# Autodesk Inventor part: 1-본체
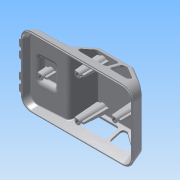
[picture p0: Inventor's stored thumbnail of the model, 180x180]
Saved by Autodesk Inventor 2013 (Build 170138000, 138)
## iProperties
Created: 2015-05
Part Number: 1-본체
Material: ABS 플라스틱
Document SubType Name: Modeling
Designer: Administrator
Density: 7.85 g/cm^3
Mass: 233.902 g
Surface Area: 305.679 cm^2
Volume: 29.7964 cm^3
Author: Administrator
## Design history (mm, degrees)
sketch "스케치1"
  geometry: L1 (0, 0)-(122, 0); L2 (42, 11.089)-(54.442, 31); L3 (54.442, 31)-(92, 31); L4 (92, 31)-(122, 11); L5 (118.738, 13.175)-(122, 1); L6 (2.144, 9)-(42, 11.089); L7 (122, 1)-(122, 0); L8 (0, 0)-(0, 1); L9 (0, 1)-(2.144, 9); L10 (0, 1)-(50, 1); L11 (0, 0)-(1, 0); L12 (1, 0)-(1, 1); L13 (1, 1)-(0, 1); L14 (0, 1)-(0, 0); L15 (122, 0)-(121, 0); L16 (121, 0)-(121, 1); L17 (121, 1)-(122, 1); L18 (122, 1)-(122, 0); L19 (122, 1)-(122, 13)
  constraints: 38 end point, 6 parallel, 3 horizontal, 3 perpendicular, 3 point on line, 1 collinear, 1 vertical
  dimensions: "d0" = 122 distance of L1.start L1.end; "d5" = 42 horizontal distance of L1.start L2.start; "d6" = 9 vertical distance of L1.start L6.start; "d7" = 125 deg angle of L2 L6; "d9" = 105 deg angle of L1 L5; "d19" = 1 distance of L1.start L8.end; "d20" = 1 distance of L5.end L1.end; "d21" = 105 deg angle of L1 L9; "d23" = 3 deg angle of L10 L6; "d24" = 1 distance of L1.start L11.end; "d25" = 1 distance of L15.end L16.end; "d26" = 1 distance of L16.end L17.end; "d70" = 30 horizontal distance of L5.end L3.end; "d76" = 31 distance between parallel lines of L1 L3; "d77" = 20 vertical distance of L3.end L4.end
extrude "돌출1" new body sketch "스케치1" stored distance "d15" = 76; taper "d16" = 0 deg
sketch "스케치3"
  geometry: L1 (13.175, 38)-(31, 38) reference; L2 (1, 38)-(13.175, 38) reference; L3 (31, -38)-(13.175, -38) reference; L4 (13.175, -38)-(1, -38) reference; L5 (31, -38)-(31, 38) reference; L6 (0, 38)-(1, 38) reference; L7 (1, -38)-(0, -38) reference; L8 (0, 38)-(1, 38); L9 (0, -38)-(1, -38); L10 (1, 38)-(31, 38); L11 (31, 38)-(31, 29.962); L12 (31, -29.962)-(31, -38); L13 (31, -38)-(1, -38); L14 (1, -38)-(1, 38) reference; L15 (31, -29.962)-(1, -38); L16 (31, 29.962)-(1, 38); 1 further point
  constraints: 16 end point, 3 collinear, 2 horizontal, 2 point on line
  dimensions: "d38" = 105 deg angle of L14 L16; "d39" = 15 deg angle of L3 L15; "d40" = 7.76457 distance from line of L1.end L16; "d41" = 65.64579 distance from line of L1.end L15
extrude "돌출3" cut sketch "스케치3" stored distance "d36" = 0; taper "d37" = 0 deg
fillet "모깎기1" dims "d42" = 12, "d44" = 3
fillet "모깎기2" dims "d45" = 3
sketch "스케치7"
  geometry: L1 (40.44, 11.007)-(13.137, 9.576) reference; L2 (10.985, 9.463)-(12.541, 14.552); L3 (12.541, 14.552)-(28.878, 15.408); L4 (28.878, 15.408)-(30.958, 10.51); L5 (10.985, 9.463)-(30.958, 10.51); L6 (4.32, 9.114)-(13.137, 9.576) reference; L7 (4.32, 9.114)-(-6, 8.573); L8 (0, 0)-(0, 8.888)
  constraints: 12 end point, 3 point on line, 1 collinear, 1 parallel, 1 vertical
  dimensions: "d59" = 70 deg angle of L1 L4; "d61" = 11 distance of L2.start L8.end; "d63" = 20 distance of L2.start L4.end; "d64" = 5 distance between parallel lines of L1 L3; "d101" = 70 deg angle of L6 L2
extrude "돌출4" join sketch "스케치7" stored distance "d65" = 26; taper "d66" = 0 deg
node "작업 평면1"
sketch "스케치15"
  geometry: L1 (13, 5)-(-13, 5) reference; L2 (-13, 0)-(-13, 5) reference; L3 (13, 5)-(13, 0) reference; L4 (-13, 0)-(-11.18, 5); L5 (-13, 5)-(-11.18, 5); L6 (-13, 5)-(-13, 0); L7 (11.18, 5)-(13, 0); L8 (13, 5)-(11.18, 5); L9 (13, 5)-(13, 0); L10 (24.829, 0)-(-24.829, 0) reference; 1 further point
  constraints: 12 end point, 3 collinear, 2 point on line, 1 perpendicular
  dimensions: "d108" = 70 deg angle of L10 L7; "d109" = 70 deg angle of L10 L4
extrude "돌출8" cut sketch "스케치15" distance "d110" = 35; taper "d111" = 0 deg
fillet "모깎기11" dims "d112" = 3
fillet "모깎기12" dims "d113" = 3
feature "쉘1" dims "d46" = 2
sketch "스케치5"
  geometry: L1 (53.253, 11)-(78.84, 11); L2 (81.84, 14)-(81.84, 23); L3 (78.84, 26)-(58.876, 26); L4 (56.332, 24.59)-(50.708, 15.59); L5 (91.092, 31)-(56.105, 31) reference; L6 (53.561, 29.59)-(42.828, 12.413) reference; L7 (107.213, 20.858)-(92.756, 30.496) reference; L8 (87.986, 11)-(103.078, 11); L9 (104.742, 16.496)-(91.242, 25.496); L10 (89.578, 26)-(87.986, 26); L11 (84.986, 23)-(84.986, 14); A1 r 3 centre (56.105, 28) between (56.105, 31) and (53.561, 29.59) reference; A2 r 3 centre (58.876, 23) between (58.876, 26) and (56.332, 24.59); A3 r 3 centre (78.84, 23) between (81.84, 23) and (78.84, 26); A4 r 3 centre (78.84, 14) between (78.84, 11) and (81.84, 14); A5 r 3 centre (53.253, 14) between (50.708, 15.59) and (53.253, 11); A6 r 3 centre (89.578, 23) between (91.242, 25.496) and (89.578, 26); A7 r 3 centre (87.986, 23) between (87.986, 26) and (84.986, 23); A8 r 3 centre (87.986, 14) between (84.986, 14) and (87.986, 11); A9 r 3 centre (103.078, 14) between (103.078, 11) and (104.742, 16.496); 5 further points
  constraints: 16 end point, 16 point on circle, 16 tangent, 9 point on line, 8 centre point, 7 equal radius, 5 parallel, 2 perpendicular, 1 collinear, 1 horizontal
  dimensions: "d47" = 5 distance between parallel lines of L3 L5; "d48" = 5 distance between parallel lines of L6 L4; "d50" = 34 distance of point (47.84, 11) point (81.84, 11); "d53" = 28 distance of point (112.986, 11) point (84.986, 11); "d54" = 5 distance between parallel lines of L9 L7; "d55" = 15 distance between parallel lines of L1 L3; "d56" = 5 distance between parallel lines of L5 L10; "d78" = 3 radius of A2
extrude "돌출5" cut sketch "스케치5" stored distance "d79" = 26; taper "d80" = 0 deg
sketch "스케치11"
  geometry: L1 (0, -2)-(98, -2) reference; L2 (0, 0)-(98, 0) reference; L3 (-12, -12)-(-12, -64) reference; L4 (98, -76)-(0, -76) reference; L5 (110, -64)-(110, -12) reference; L6 (109, -12)-(109, -64); L7 (98, -75)-(0, -75); L8 (-11, -64)-(-11, -12); L9 (0, -1)-(98, -1); A1 r 12 centre (98, -12) between (110, -12) and (98, 0) reference; A2 r 12 centre (0, -12) between (0, 0) and (-12, -12) reference; A3 r 12 centre (0, -64) between (-12, -64) and (0, -76) reference; A4 r 12 centre (98, -64) between (98, -76) and (110, -64) reference; A5 r 11 centre (98, -12) between (109, -12) and (98, -1); A6 r 11 centre (98, -64) between (98, -75) and (109, -64); A7 r 11 centre (0, -64) between (-11, -64) and (0, -75); A8 r 11 centre (0, -12) between (0, -1) and (-11, -12); 1 further point
  constraints: 8 end point, 8 point on circle, 4 centre point, 7 other
  dimensions: "d82" = 1 distance between parallel lines of L1 L9
extrude "돌출6" cut sketch "스케치11" distance "d83" = 1; taper "d84" = 0 deg
sketch "스케치12"
  geometry: L1 (-12, -64)-(-12, -12) reference; L2 (110, -64)-(110, -12) reference; C1 r 3 at (49, -16); C2 r 3 at (89, -38); C3 r 3 at (9, -38); C4 r 3 at (49, -60); 3 further points
  constraints: 4 centre point, 3 equal radius, 2 horizontal alignment, 2 midpoint, 1 vertical alignment
  dimensions: "d85" = 6 diameter of C1; "d87" = 22 vertical distance of point (-12, -38) C1.centre; "d88" = 21 distance from line of L2 C2.centre; "d90" = 40 horizontal distance of C1.centre C2.centre; "d91" = 40 horizontal distance of C3.centre C1.centre; "d92" = 22 vertical distance of point (-12, -38) C4.centre (= d87)
extrude "돌출7" join sketch "스케치12" stored distance "d93" = 1; taper "d94" = 2 deg
node "작업 평면2"
sketch "스케치16"
  geometry: L1 (-5, 1)-(5, 1); L2 (5, 1)-(5, -1); L3 (5, -1)-(-5, -1); L4 (-5, -1)-(-5, 1); L5 (-5, 1)-(5, -1); L6 (5, 1)-(-5, -1); L7 (-5, 45)-(5, 45); L8 (5, 45)-(5, 43); L9 (5, 43)-(-5, 43); L10 (-5, 43)-(-5, 45); L11 (-5, 45)-(5, 43); L12 (5, 45)-(-5, 43); L13 (35, 23)-(45, 23); L14 (45, 23)-(45, 21); L15 (45, 21)-(35, 21); L16 (35, 21)-(35, 23); L17 (35, 23)-(45, 21); L18 (45, 23)-(35, 21); L19 (-45, 23)-(-35, 23); L20 (-35, 23)-(-35, 21); L21 (-35, 21)-(-45, 21); L22 (-45, 21)-(-45, 23); L23 (-45, 23)-(-35, 21); L24 (-35, 23)-(-45, 21); C1 r 3 at (0, 44) reference; C2 r 3 at (40, 22) reference; C3 r 3 at (-40, 22) reference; C4 r 3 at (0, 0) reference; 1 further point
  constraints: 48 end point, 8 midpoint, 8 parallel, 4 horizontal, 4 perpendicular
  dimensions: "d115" = 10 distance of L1.start L1.end; "d117" = 2 distance of L1.end L2.end; "d118" = 10 horizontal distance of L19.end L21.end; "d119" = 2 distance of L19.end L20.end; "d120" = 10 distance of L8.end L9.end; "d121" = 2 distance of L7.end L8.end; "d122" = 10 distance of L13.start L13.end; "d123" = 2 distance of L13.end L14.end
extrude "돌출9" join sketch "스케치16" stored distance "d124" = 35; taper "d125" = 2.5 deg
hole "구멍1" diameter "d128" = 3.242; stored, may be unused: countersink angle "d132" = 90 deg, drill point angle "d134" = 118 deg; dims "d126" = 10, "d127" = 10, "d129" = 9, "d130" = 4, "d131" = 2, "d133" = 11
hole "구멍2" diameter "d137" = 3.242; stored, may be unused: countersink angle "d141" = 90 deg, drill point angle "d143" = 118 deg; dims "d135" = 10, "d136" = 10, "d138" = 9, "d139" = 4, "d140" = 2, "d142" = 11
hole "구멍3" diameter "d146" = 3.242; stored, may be unused: countersink angle "d150" = 90 deg, drill point angle "d152" = 118 deg; dims "d144" = 10, "d145" = 10, "d147" = 9, "d148" = 4, "d149" = 2, "d151" = 11
hole "구멍4" diameter "d155" = 3.242; stored, may be unused: countersink angle "d159" = 90 deg, drill point angle "d161" = 118 deg; dims "d153" = 10, "d154" = 10, "d156" = 9, "d157" = 4, "d158" = 2, "d160" = 11
sketch "스케치18"
  geometry: A1 r 4 centre (1, -21) between (1, -25) and (1, -17); A2 r 4 centre (1, -10) between (1, -14) and (1, -6); A3 r 4 centre (1, 10) between (1, 6) and (1, 14); A4 r 4 centre (1, 21) between (1, 17) and (1, 25); 3 further points
  constraints: 8 point on circle, 4 centre point, 3 equal radius, 13 other
  dimensions: "d162" = 10 vertical distance of A2.centre point (0, 0); "d163" = 11 distance of A1.centre A2.centre; "d164" = 10 vertical distance of point (0, 0) A3.centre (derived); "d165" = 11 distance of A3.centre A4.centre; "d167" = 4 radius of A1
extrude "돌출10" join sketch "스케치18" distance "d168" = 1; taper "d170" = 0 deg; dims "d169" = 2, "d171" = 0
chamfer "모따기1" distance "d172" = 1; stored, may be unused: second distance "d173" = 2, angle "d174" = 45 deg
sketch "스케치19"
  geometry: L1 (34.987, 55.319)-(34.987, 0) reference; L2 (65.895, 53.66)-(65.895, 1.66) reference; 3 further points
  constraints: 1 horizontal alignment, 1 midpoint, 1 other
  dimensions: "d175" = 50 distance from line of point (15.895, 27.66) L2
feature "엠보싱1" sketch "스케치19" dims "d0" = 122, "d5" = 42, "d6" = 9, "d7" = 125 deg, "d9" = 105 deg, "d19" = 1, "d20" = 1, "d21" = 105 deg, "d23" = 3 deg, "d24" = 1, "d25" = 1, "d26" = 1, "d70" = 30, "d76" = 31, "d77" = 20, "d176" = 0.5, "d177" = 0
node "솔리드1"
node "투영된 루프2"
node "투영된 루프3"
node "투영된 루프4"
other parameters: "d106" = 90 deg, "d114" = -2
